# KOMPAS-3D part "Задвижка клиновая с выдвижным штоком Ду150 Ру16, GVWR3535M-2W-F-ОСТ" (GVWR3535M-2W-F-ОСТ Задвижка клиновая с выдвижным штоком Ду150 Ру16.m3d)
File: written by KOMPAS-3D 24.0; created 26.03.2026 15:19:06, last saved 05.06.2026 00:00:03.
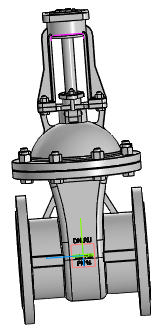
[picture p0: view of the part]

Document properties: Автор: R2D2; Полное имя файла: E:\Работа\Зайцев\GVWR3535M-2W-F-ОСТ Задвижка клиновая 30нж941нж DN.ru Ду50-200 Ру16\исходные данные\DN150\GVWR3535M-2W-F-ОСТ Задвижка клиновая с выдвижным штоком Ду150 Ру16.m3d

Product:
- Component [detail]: ANSI B18.2.4.2M - M16x2 - 24  | designation ANSI B18.2.4.2M - M16x2  | qty 8  | pos. 2  | Комментарий: Типы метрических   шестигранных гаек   2; Автор: R2D2; additional columns: Сталь, мягкая; source file: ANSI B18.2.4.2M - M16x2 ANSI B18.2.4.2M - M16x2 - 24.m3d
- Component [detail]: AS 1110 - M16 x 60  | qty 8  | pos. 3  | Комментарий: Болты и винты   шестигранные точные   метрические ISO; Автор: R2D2; additional columns: Сталь, мягкая; source file: AS 1110 - M16 x 60 AS 1110 - M16 x 60.m3d
- Component [detail]: AS 1110 - M10 x 35  | qty 4  | pos. 4  | Комментарий: Болты и винты   шестигранные точные   метрические ISO; Автор: R2D2; additional columns: Сталь, мягкая; source file: AS 1110 - M10 x 35 AS 1110 - M10 x 35.m3d
- Component [detail]: ANSI B18.2.4.2M - M10x1,5 - 16  | designation ANSI B18.2.4.2M - M10x1,5  | qty 4  | pos. 5  | Комментарий: Типы метрических   шестигранных гаек   2; Автор: R2D2; additional columns: Сталь, мягкая; source file: ANSI B18.2.4.2M - M10x1,5 ANSI B18.2.4.2M - M10x1,5 - 16.m3d
- Component [detail]: ANSI B18.2.4.2M - M8x1,25 - 13  | designation ANSI B18.2.4.2M - M8x1,25  | qty 1  | pos. 6  | Комментарий: Типы метрических   шестигранных гаек   2; Автор: R2D2; additional columns: Сталь, мягкая; source file: ANSI B18.2.4.2M - M8x1,25 ANSI B18.2.4.2M - M8x1,25 - 13.m3d
- Component [detail]: Деталь1  | qty 1  | pos. 7  | Автор: R2D2; additional columns: Типовые; source file: 2.m3d
- Component [detail]: Фланец  | qty 1  | pos. 8  | Автор: R2D2; additional columns: Типовые; source file: Фланец DN150 PN16 b24.m3d
- Component [detail]: Фланец  | qty 1  | pos. 9  | Автор: R2D2; additional columns: Типовые; source file: Фланец DN150 PN16 b24.m3d
- Component [detail]: ANSI B18.2.4.2M - M8x1,25 - 13  | designation ANSI B18.2.4.2M - M8x1,25-01  | qty 1  | pos. 6  | Комментарий: Типы метрических   шестигранных гаек   2; Автор: R2D2; additional columns: Сталь, мягкая; source file: ANSI B18.2.4.2M - M8x1,25 ANSI B18.2.4.2M - M8x1,25 - 13.m3d
- Component [assembly]: DN50_3D_STEP  | designation Сборка  | qty 1  | Масса: 2.725126; Автор: R2D2; source file: Фланец А.a3d
- Body: Тело 1  | qty 1
    Масса: 97.662068
- Part/product: Задвижка клиновая с выдвижным штоком Ду150 Ру16  | designation GVWR3535M-2W-F-ОСТ
    Масса: 47.5
    Раздел спецификации: Прочие изделия
    Примечание: D040-09829
    additional columns: D040-10013

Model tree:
1. Массив по сетке:2  (labels: Грань.Твердое тело1; Вершина.Твердое тело1)  (4 pattern instances)
     Шаг 1 = 50; Угол раствора = 90; Шаг 2 = 120
2. Массив по концентрической сетке:1  (labels: Грань.Твердое тело1)  (8 pattern instances)
     Шаг 2 = 360
3. Элемент выдавливания:1  (with: Грань.Элемент выдавливания:2, Грань.Элемент вращения:1)
     Расстояние 1 = 7.98292
4. Элемент выдавливания:2  (with: Грань.Элемент выдавливания:1, Грань.Элемент вращения:1)
     Расстояние 1 = 9.95192
5. Скругление:1  (with: Ребро.Элемент выдавливания:2, Ребро.Элемент выдавливания:1)
     Радиус = 3
6. Элемент выдавливания:3  (with: Грань.Элемент выдавливания:1)
     Расстояние 1 = 60
7. Эскиз:1  (with: Вершина.Элемент выдавливания:3)
8. Элемент по траектории:1  (with: Грань.Элемент выдавливания:3)
     Длина траектории = 90.708
9. Элемент выдавливания:4  (with: Грань.Элемент выдавливания:1, Грань.Элемент по траектории:1)
     Расстояние 1 = 126.696
10. Эскиз:2
11. Элемент выдавливания:5  (with: Грань.Элемент выдавливания:1, Грань.Элемент вращения:1, Грань.Операция без истории:2)  (labels: Грань.Твердое тело1; Грань.Solid1; Solid1; Твердое тело1)
     Расстояние 1 = 98.5; Смещение 1 = 1; Расстояние = -140; Ориентация = 2; Ориентация = 2; Расстояние = -539

Referenced files in E:\Работа\Зайцев\GVWR3535M-2W-F-ОСТ Задвижка клиновая 30нж941нж DN.ru Ду50-200 Ру16\исходные данные\DN150\: ANSI B18.2.4.2M - M16x2 ANSI B18.2.4.2M - M16x2 - 24.m3d, AS 1110 - M16 x 60 AS 1110 - M16 x 60.m3d, AS 1110 - M10 x 35 AS 1110 - M10 x 35.m3d, ANSI B18.2.4.2M - M10x1,5 ANSI B18.2.4.2M - M10x1,5 - 16.m3d, ANSI B18.2.4.2M - M8x1,25 ANSI B18.2.4.2M - M8x1,25 - 13.m3d, 2.m3d, Фланец DN150 PN16 b24.m3d, Фланец А.a3d
Referenced files in E:\Работа\Зайцев\GVWR2626M-2W-F-S Задвижка клиновая с выдвижным штоком DN.ru Ду50-300 Ру16\DN150\исходные материалы\: Фланец DN150 PN16 b24.m3d
Referenced files in E:\Работа\Зайцев\GVWR3131M-2W-F-S Задвижка клиновая с выдвижным штоком DN.ru Ду50-200 Ру63\DN150\исходные материалы\: ANSI B18.2.4.2M - M10x1,5 ANSI B18.2.4.2M - M10x1,5 - 16.m3d, AS 1110 - M10 x 35 AS 1110 - M10 x 35.m3d, ANSI B18.2.4.2M - M16x2 ANSI B18.2.4.2M - M16x2 - 24.m3d, AS 1110 - M16 x 60 AS 1110 - M16 x 60.m3d
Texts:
  GVWR3535M-2W-F-ОСТ
  DN150
  GOST 26.020 Pr3
  PN16
  ANSI B18.2.4.2M - M16x2 ANSI B18.2.4.2M - M16x2 - 24 (1)
  AS 1110 - M16 x 60 AS 1110 - M16 x 60 (1)
  AS 1110 - M10 x 35 AS 1110 - M10 x 35 (1)
  ANSI B18.2.4.2M - M10x1,5 ANSI B18.2.4.2M - M10x1,5 - 16 (1)
  ANSI B18.2.4.2M - M8x1,25 ANSI B18.2.4.2M - M8x1,25 - 13
  Деталь1 Деталь1
  Фланец (1)
  Фланец (2)
  ANSI B18.2.4.2M - M8x1,25-01 ANSI B18.2.4.2M - M8x1,25 - 13
  Сборка DN50_3D_STEP
  Ось Z.Начало координат
  Ось Y.Начало координат
  Плоскость ZY.Начало координат
  Плоскость ZX.Начало координат
  Плоскость XY.Начало координат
